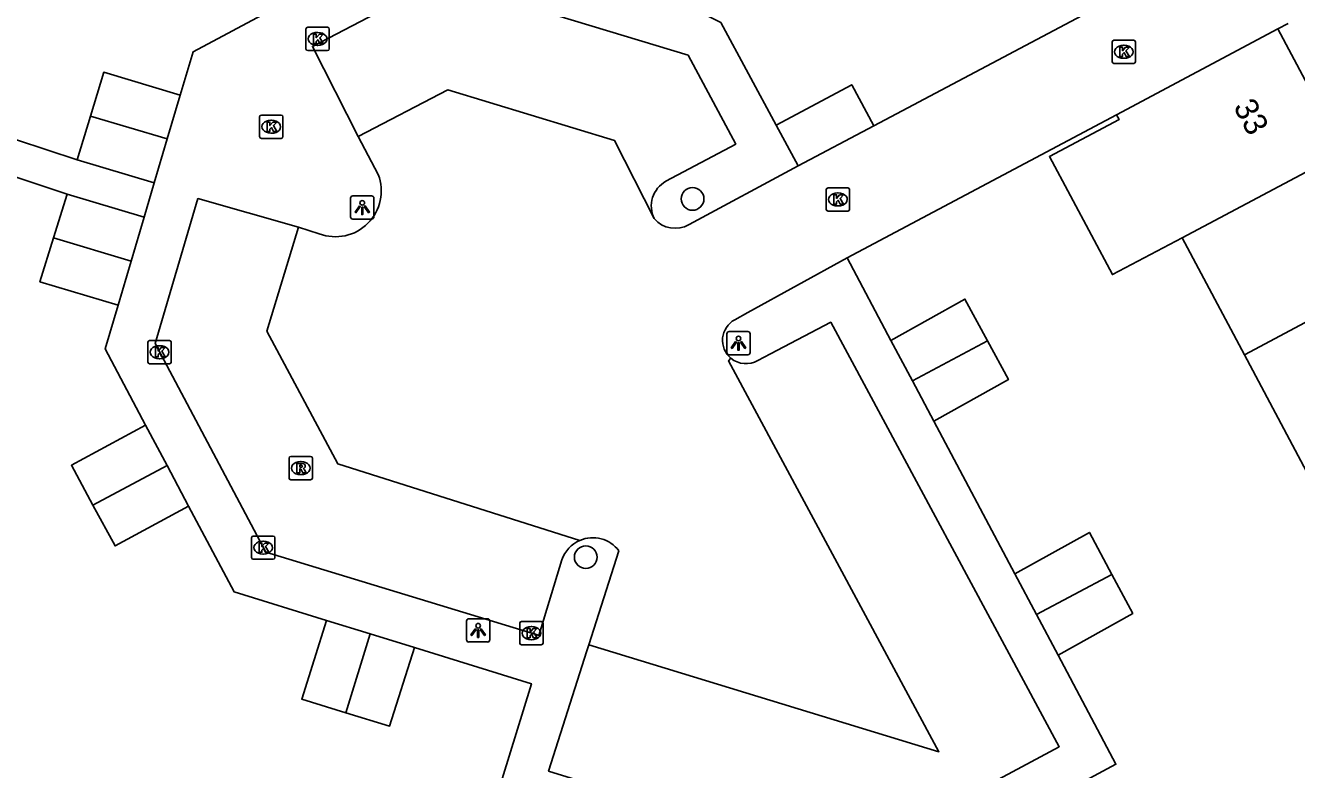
# Model space of a CAD drawing. Extents: x 160304 to 160954, y 383686 to 384161.
# Drawn here: x 160632.9 to 160687.5, y 383830.6 to 383862.6 of the extents above; entities that cross this region are included whole.
import ezdxf

# ---------------------------------------------------------------- set-up
doc = ezdxf.new("R2010")
doc.units = 0
for name, color, linetype in [('IMGEO_Boom', 7, 'Continuous'), ('IMGEO_Kolk', 7, 'Continuous'), ('IMGEO_Lichtpunt', 7, 'Continuous'), ('IMGEO_Pand', 7, 'Continuous'), ('IMGEO_Pand_nummerreeks', 7, 'Continuous'), ('IMGEO_Rijbaan_lokaal_open', 7, 'Continuous'), ('IMGEO_Rioolput', 7, 'Continuous'), ('IMGEO_Voetpad_open', 7, 'Continuous')]:
    doc.layers.add(name, color=color, linetype=linetype)

msp = doc.modelspace()

# ---------------------------------------------------------------- linework, layer by layer
at = {"layer": 'IMGEO_Boom'}
for centre in [(160661.512, 383855.124), (160656.926, 383839.727)]:
    msp.add_circle(centre, 0.489, dxfattribs=at)
at = {"layer": 'IMGEO_Kolk'}
for p, q in [((160644.981, 383862.498), (160645.833, 383862.498)), ((160644.906, 383861.572), (160644.906, 383862.424)), ((160645.394, 383862.278), (160645.419, 383862.278)), ((160645.907, 383862.424), (160645.907, 383861.572)), ((160679.616, 383861.945), (160680.468, 383861.945)), ((160645.833, 383861.498), (160644.981, 383861.498)), ((160645.417, 383861.718), (160645.392, 383861.718)), ((160679.541, 383861.019), (160679.541, 383861.871)), ((160680.029, 383861.725), (160680.054, 383861.725)), ((160680.542, 383861.871), (160680.542, 383861.019)), ((160680.468, 383860.945), (160679.616, 383860.945)), ((160680.052, 383861.165), (160680.027, 383861.165)), ((160642.913, 383857.8), (160642.913, 383858.652)), ((160642.988, 383858.726), (160643.84, 383858.726)), ((160643.914, 383858.652), (160643.914, 383857.8)), ((160643.401, 383858.506), (160643.426, 383858.506)), ((160643.84, 383857.726), (160642.988, 383857.726)), ((160643.424, 383857.946), (160643.399, 383857.946)), ((160667.259, 383854.673), (160667.259, 383855.525)), ((160667.334, 383855.599), (160668.186, 383855.599)), ((160667.747, 383855.379), (160667.772, 383855.379)), ((160668.26, 383855.525), (160668.26, 383854.673)), ((160667.77, 383854.819), (160667.745, 383854.819)), ((160668.186, 383854.599), (160667.334, 383854.599)), ((160638.115, 383848.11), (160638.115, 383848.962)), ((160638.19, 383849.036), (160639.042, 383849.036)), ((160638.603, 383848.816), (160638.628, 383848.816)), ((160639.116, 383848.962), (160639.116, 383848.11)), ((160639.042, 383848.036), (160638.19, 383848.036)), ((160638.626, 383848.256), (160638.601, 383848.256)), ((160642.643, 383840.636), (160643.495, 383840.636)), ((160642.568, 383839.71), (160642.568, 383840.562)), ((160643.056, 383840.416), (160643.081, 383840.416)), ((160643.569, 383840.562), (160643.569, 383839.71)), ((160643.495, 383839.636), (160642.643, 383839.636)), ((160643.079, 383839.856), (160643.054, 383839.856)), ((160654.088, 383836.035), (160654.088, 383836.887)), ((160654.163, 383836.961), (160655.015, 383836.961)), ((160655.089, 383836.887), (160655.089, 383836.035)), ((160654.576, 383836.741), (160654.601, 383836.741)), ((160655.015, 383835.961), (160654.163, 383835.961)), ((160654.599, 383836.181), (160654.574, 383836.181))]:
    msp.add_line(p, q, dxfattribs=at)
for points in [[(160644.981, 383862.498), (160645.833, 383862.498)], [(160644.906, 383861.572), (160644.906, 383862.424)], [(160645.227, 383862.198), (160645.35, 383862.198), (160645.35, 383862.047), (160645.48, 383862.198), (160645.644, 383862.198), (160645.498, 383862.047), (160645.651, 383861.798), (160645.499, 383861.798), (160645.414, 383861.962), (160645.35, 383861.895), (160645.35, 383861.798), (160645.227, 383861.798), (160645.227, 383862.198)], [(160645.907, 383862.424), (160645.907, 383861.572)], [(160679.616, 383861.945), (160680.468, 383861.945)], [(160645.833, 383861.498), (160644.981, 383861.498)], [(160679.541, 383861.019), (160679.541, 383861.871)], [(160679.862, 383861.645), (160679.985, 383861.645), (160679.985, 383861.494), (160680.115, 383861.645), (160680.279, 383861.645), (160680.133, 383861.494), (160680.286, 383861.245), (160680.134, 383861.245), (160680.049, 383861.409), (160679.985, 383861.342), (160679.985, 383861.245), (160679.862, 383861.245), (160679.862, 383861.645)], [(160680.542, 383861.871), (160680.542, 383861.019)], [(160680.468, 383860.945), (160679.616, 383860.945)], [(160642.913, 383857.8), (160642.913, 383858.652)], [(160642.988, 383858.726), (160643.84, 383858.726)], [(160643.914, 383858.652), (160643.914, 383857.8)], [(160643.234, 383858.426), (160643.357, 383858.426), (160643.357, 383858.275), (160643.487, 383858.426), (160643.651, 383858.426), (160643.505, 383858.275), (160643.658, 383858.026), (160643.506, 383858.026), (160643.421, 383858.19), (160643.357, 383858.123), (160643.357, 383858.026), (160643.234, 383858.026), (160643.234, 383858.426)], [(160643.84, 383857.726), (160642.988, 383857.726)], [(160667.259, 383854.673), (160667.259, 383855.525)], [(160667.334, 383855.599), (160668.186, 383855.599)], [(160668.26, 383855.525), (160668.26, 383854.673)], [(160667.58, 383855.299), (160667.703, 383855.299), (160667.703, 383855.148), (160667.833, 383855.299), (160667.997, 383855.299), (160667.851, 383855.148), (160668.004, 383854.899), (160667.852, 383854.899), (160667.767, 383855.063), (160667.703, 383854.996), (160667.703, 383854.899), (160667.58, 383854.899), (160667.58, 383855.299)], [(160668.186, 383854.599), (160667.334, 383854.599)], [(160638.115, 383848.11), (160638.115, 383848.962)], [(160638.19, 383849.036), (160639.042, 383849.036)], [(160639.116, 383848.962), (160639.116, 383848.11)], [(160638.436, 383848.736), (160638.559, 383848.736), (160638.559, 383848.585), (160638.689, 383848.736), (160638.853, 383848.736), (160638.707, 383848.585), (160638.86, 383848.336), (160638.708, 383848.336), (160638.623, 383848.5), (160638.559, 383848.433), (160638.559, 383848.336), (160638.436, 383848.336), (160638.436, 383848.736)], [(160639.042, 383848.036), (160638.19, 383848.036)], [(160642.643, 383840.636), (160643.495, 383840.636)], [(160642.568, 383839.71), (160642.568, 383840.562)], [(160642.889, 383840.336), (160643.012, 383840.336), (160643.012, 383840.185), (160643.142, 383840.336), (160643.306, 383840.336), (160643.16, 383840.185), (160643.313, 383839.936), (160643.161, 383839.936), (160643.076, 383840.1), (160643.012, 383840.033), (160643.012, 383839.936), (160642.889, 383839.936), (160642.889, 383840.336)], [(160643.569, 383840.562), (160643.569, 383839.71)], [(160643.495, 383839.636), (160642.643, 383839.636)], [(160654.088, 383836.035), (160654.088, 383836.887)], [(160654.163, 383836.961), (160655.015, 383836.961)], [(160655.089, 383836.887), (160655.089, 383836.035)], [(160654.409, 383836.661), (160654.532, 383836.661), (160654.532, 383836.51), (160654.662, 383836.661), (160654.826, 383836.661), (160654.68, 383836.51), (160654.833, 383836.261), (160654.681, 383836.261), (160654.596, 383836.425), (160654.532, 383836.358), (160654.532, 383836.261), (160654.409, 383836.261), (160654.409, 383836.661)], [(160655.015, 383835.961), (160654.163, 383835.961)]]:
    msp.add_lwpolyline(points, dxfattribs=at)
for centre, start, end in [((160644.983, 383862.422), 91.552, 178.448), ((160644.983, 383862.422), 91.552, 178.448), ((160645.831, 383862.422), 1.552, 88.448), ((160645.831, 383862.422), 1.552, 88.448), ((160679.618, 383861.869), 91.552, 178.448), ((160679.618, 383861.869), 91.552, 178.448), ((160680.466, 383861.869), 1.552, 88.448), ((160680.466, 383861.869), 1.552, 88.448), ((160644.983, 383861.574), 181.552, 268.448), ((160644.983, 383861.574), 181.552, 268.448), ((160645.831, 383861.574), 271.552, 358.448), ((160645.831, 383861.574), 271.552, 358.448), ((160679.618, 383861.021), 181.552, 268.448), ((160679.618, 383861.021), 181.552, 268.448), ((160680.466, 383861.021), 271.552, 358.448), ((160680.466, 383861.021), 271.552, 358.448), ((160642.99, 383858.65), 91.552, 178.448), ((160642.99, 383858.65), 91.552, 178.448), ((160643.838, 383858.65), 1.552, 88.448), ((160643.838, 383858.65), 1.552, 88.448), ((160642.99, 383857.802), 181.552, 268.448), ((160642.99, 383857.802), 181.552, 268.448), ((160643.838, 383857.802), 271.552, 358.448), ((160643.838, 383857.802), 271.552, 358.448), ((160667.336, 383855.523), 91.552, 178.448), ((160667.336, 383855.523), 91.552, 178.448), ((160668.184, 383855.523), 1.552, 88.448), ((160668.184, 383855.523), 1.552, 88.448), ((160667.336, 383854.675), 181.552, 268.448), ((160667.336, 383854.675), 181.552, 268.448), ((160668.184, 383854.675), 271.552, 358.448), ((160668.184, 383854.675), 271.552, 358.448), ((160638.192, 383848.96), 91.552, 178.448), ((160638.192, 383848.96), 91.552, 178.448), ((160639.04, 383848.96), 1.552, 88.448), ((160639.04, 383848.96), 1.552, 88.448), ((160638.192, 383848.112), 181.552, 268.448), ((160638.192, 383848.112), 181.552, 268.448), ((160639.04, 383848.112), 271.552, 358.448), ((160639.04, 383848.112), 271.552, 358.448), ((160642.645, 383840.56), 91.552, 178.448), ((160642.645, 383840.56), 91.552, 178.448), ((160643.493, 383840.56), 1.552, 88.448), ((160643.493, 383840.56), 1.552, 88.448), ((160642.645, 383839.712), 181.552, 268.448), ((160642.645, 383839.712), 181.552, 268.448), ((160643.493, 383839.712), 271.552, 358.448), ((160643.493, 383839.712), 271.552, 358.448), ((160654.165, 383836.885), 91.552, 178.448), ((160654.165, 383836.885), 91.552, 178.448), ((160655.013, 383836.885), 1.552, 88.448), ((160655.013, 383836.885), 1.552, 88.448), ((160654.165, 383836.037), 181.552, 268.448), ((160654.165, 383836.037), 181.552, 268.448), ((160655.013, 383836.037), 271.552, 358.448), ((160655.013, 383836.037), 271.552, 358.448)]:
    msp.add_arc(centre, 0.0765, start, end, dxfattribs=at)
for centre, major_axis, ratio, start_param, end_param in [((160645.393, 383861.998), (-0.387, 0.002), 0.722429, 4.712389, 7.853982), ((160645.418, 383861.998), (-0.39, 0.002), 0.717154, 1.570796, 4.712389), ((160680.028, 383861.445), (-0.387, 0.002), 0.722429, 4.712389, 7.853982), ((160680.053, 383861.445), (-0.39, 0.002), 0.717154, 1.570796, 4.712389), ((160643.4, 383858.226), (-0.387, 0.002), 0.722429, 4.712389, 7.853982), ((160643.425, 383858.226), (-0.39, 0.002), 0.717154, 1.570796, 4.712389), ((160667.746, 383855.099), (-0.387, 0.002), 0.722429, 4.712389, 7.853982), ((160667.771, 383855.099), (-0.39, 0.002), 0.717154, 1.570796, 4.712389), ((160638.602, 383848.536), (-0.387, 0.002), 0.722429, 4.712389, 7.853982), ((160638.627, 383848.536), (-0.39, 0.002), 0.717154, 1.570796, 4.712389), ((160643.055, 383840.136), (-0.387, 0.002), 0.722429, 4.712389, 7.853982), ((160643.08, 383840.136), (-0.39, 0.002), 0.717154, 1.570796, 4.712389), ((160654.575, 383836.461), (-0.387, 0.002), 0.722429, 4.712389, 7.853982), ((160654.6, 383836.461), (-0.39, 0.002), 0.717154, 1.570796, 4.712389)]:
    msp.add_ellipse(centre, major_axis=major_axis, ratio=ratio, start_param=start_param, end_param=end_param, dxfattribs=at)
at = {"layer": 'IMGEO_Lichtpunt'}
for p, q in [((160646.825, 383855.156), (160646.825, 383854.349)), ((160646.825, 383855.156), (160646.825, 383854.349)), ((160647.727, 383855.251), (160646.919, 383855.251)), ((160647.727, 383855.251), (160646.919, 383855.251)), ((160647.821, 383854.349), (160647.821, 383855.156)), ((160647.821, 383854.349), (160647.821, 383855.156)), ((160646.919, 383854.255), (160647.727, 383854.255)), ((160646.919, 383854.255), (160647.727, 383854.255)), ((160663.891, 383849.421), (160663.083, 383849.421)), ((160663.891, 383849.421), (160663.083, 383849.421)), ((160662.989, 383849.326), (160662.989, 383848.519)), ((160662.989, 383849.326), (160662.989, 383848.519)), ((160663.985, 383848.519), (160663.985, 383849.326)), ((160663.985, 383848.519), (160663.985, 383849.326)), ((160663.083, 383848.425), (160663.891, 383848.425)), ((160663.083, 383848.425), (160663.891, 383848.425)), ((160651.804, 383836.983), (160651.804, 383836.176)), ((160651.804, 383836.983), (160651.804, 383836.176)), ((160652.706, 383837.078), (160651.898, 383837.078)), ((160652.706, 383837.078), (160651.898, 383837.078)), ((160652.8, 383836.176), (160652.8, 383836.983)), ((160652.8, 383836.176), (160652.8, 383836.983)), ((160651.898, 383836.082), (160652.706, 383836.082)), ((160651.898, 383836.082), (160652.706, 383836.082))]:
    msp.add_line(p, q, dxfattribs=at)
for points in [[(160647.199, 383854.82), (160647.238, 383854.792), (160647.05, 383854.53), (160647.012, 383854.557), (160647.199, 383854.82)], [(160647.411, 383854.792), (160647.449, 383854.819), (160647.636, 383854.557), (160647.597, 383854.529), (160647.411, 383854.792)], [(160647.301, 383854.772), (160647.348, 383854.772), (160647.348, 383854.45), (160647.301, 383854.45), (160647.301, 383854.772)], [(160663.363, 383848.99), (160663.402, 383848.962), (160663.214, 383848.7), (160663.176, 383848.727), (160663.363, 383848.99)], [(160663.465, 383848.942), (160663.512, 383848.942), (160663.512, 383848.62), (160663.465, 383848.62), (160663.465, 383848.942)], [(160663.575, 383848.962), (160663.613, 383848.989), (160663.8, 383848.727), (160663.761, 383848.699), (160663.575, 383848.962)], [(160652.178, 383836.647), (160652.217, 383836.619), (160652.029, 383836.357), (160651.991, 383836.384), (160652.178, 383836.647)], [(160652.28, 383836.599), (160652.327, 383836.599), (160652.327, 383836.277), (160652.28, 383836.277), (160652.28, 383836.599)], [(160652.39, 383836.619), (160652.428, 383836.646), (160652.615, 383836.384), (160652.576, 383836.356), (160652.39, 383836.619)]]:
    msp.add_lwpolyline(points, dxfattribs=at)
for centre in [(160647.324, 383854.954), (160663.488, 383849.124), (160652.303, 383836.781)]:
    msp.add_circle(centre, 0.0994, dxfattribs=at)
for centre, start, end in [((160646.919, 383855.156), 90, 180), ((160646.919, 383855.156), 90, 180), ((160647.727, 383855.156), 0, 90), ((160647.727, 383855.156), 0, 90), ((160646.919, 383854.349), 180, 270), ((160646.919, 383854.349), 180, 270), ((160647.727, 383854.349), 270, 0), ((160647.727, 383854.349), 270, 360), ((160663.083, 383849.326), 90, 180), ((160663.083, 383849.326), 90, 180), ((160663.891, 383849.326), 0, 90), ((160663.891, 383849.326), 0, 90), ((160663.083, 383848.519), 180, 270), ((160663.083, 383848.519), 180, 270), ((160663.891, 383848.519), 270, 0), ((160663.891, 383848.519), 270, 360), ((160651.898, 383836.983), 90, 180), ((160651.898, 383836.983), 90, 180), ((160652.706, 383836.983), 0, 90), ((160652.706, 383836.983), 0, 90), ((160651.898, 383836.176), 180, 270), ((160651.898, 383836.176), 180, 270), ((160652.706, 383836.176), 270, 0), ((160652.706, 383836.176), 270, 360)]:
    msp.add_arc(centre, 0.0946, start, end, dxfattribs=at)
at = {"layer": 'IMGEO_Pand'}
for points in [[(160686.663, 383862.43), (160679.729, 383858.737)], [(160689.481, 383857.138), (160686.663, 383862.43)], [(160635.644, 383858.686), (160636.219, 383860.57), (160639.506, 383859.586)], [(160665.106, 383858.297), (160668.35, 383860.032), (160669.297, 383858.262)], [(160639.506, 383859.586), (160638.947, 383857.698)], [(160635.069, 383856.802), (160635.644, 383858.686)], [(160638.947, 383857.698), (160635.644, 383858.686)], [(160679.729, 383858.737), (160679.836, 383858.535), (160676.845, 383856.942), (160679.547, 383851.868), (160682.541, 383853.456)], [(160666.055, 383856.543), (160665.106, 383858.297)], [(160669.297, 383858.262), (160666.055, 383856.543)], [(160638.947, 383857.698), (160638.388, 383855.809)], [(160682.541, 383853.456), (160689.481, 383857.138)], [(160638.388, 383855.809), (160635.069, 383856.802)], [(160634.058, 383853.448), (160634.642, 383855.331)], [(160634.642, 383855.331), (160637.955, 383854.343)], [(160637.955, 383854.343), (160637.396, 383852.452)], [(160636.837, 383850.561), (160633.474, 383851.564), (160634.058, 383853.448)], [(160634.058, 383853.448), (160637.396, 383852.452)], [(160682.541, 383853.456), (160685.222, 383848.423)], [(160637.396, 383852.452), (160636.837, 383850.561)], [(160685.222, 383848.423), (160692.156, 383852.115)], [(160674.186, 383849.023), (160673.216, 383850.817), (160670.036, 383849.043)], [(160670.956, 383847.31), (160670.036, 383849.043)], [(160674.186, 383849.023), (160670.956, 383847.31)], [(160671.878, 383845.572), (160675.085, 383847.361), (160674.186, 383849.023)], [(160685.222, 383848.423), (160687.891, 383843.41)], [(160671.878, 383845.572), (160670.956, 383847.31)], [(160635.753, 383841.969), (160634.828, 383843.676), (160638.017, 383845.404)], [(160638.017, 383845.404), (160638.941, 383843.661)], [(160635.753, 383841.969), (160638.941, 383843.661)], [(160638.941, 383843.661), (160639.864, 383841.919)], [(160639.864, 383841.919), (160636.708, 383840.209), (160635.753, 383841.969)], [(160679.531, 383838.979), (160678.564, 383840.791), (160675.364, 383839.006)], [(160676.289, 383837.262), (160675.364, 383839.006)], [(160676.289, 383837.262), (160679.531, 383838.979)], [(160677.215, 383835.517), (160680.423, 383837.307), (160679.531, 383838.979)], [(160646.621, 383833.04), (160644.721, 383833.621), (160645.787, 383837.008)], [(160645.787, 383837.008), (160647.67, 383836.426)], [(160677.215, 383835.517), (160676.289, 383837.262)], [(160647.67, 383836.426), (160646.621, 383833.04)], [(160647.67, 383836.426), (160649.562, 383835.841)], [(160649.562, 383835.841), (160648.5, 383832.466), (160646.621, 383833.04)]]:
    msp.add_lwpolyline(points, dxfattribs=at)
at = {"layer": 'IMGEO_Rijbaan_lokaal_open'}
for points in [[(160669.297, 383858.262), (160685.008, 383866.594)], [(160686.663, 383862.43), (160687.096, 383862.66)], [(160647.154, 383857.81), (160650.995, 383859.816), (160658.161, 383857.635), (160659.864, 383854.277)], [(160668.151, 383852.596), (160679.729, 383858.737)], [(160648.012, 383856.169), (160647.154, 383857.81)], [(160661.361, 383854.018), (160666.055, 383856.543)], [(160656.67, 383840.446), (160646.268, 383843.745), (160643.228, 383849.443), (160644.589, 383853.907)], [(160644.589, 383853.907), (160645.477, 383853.625)], [(160668.151, 383852.596), (160663.89, 383850.24), (160663.326, 383849.928)], [(160657.06, 383835.957), (160672.095, 383831.365), (160663.061, 383848.16), (160663.159, 383848.277)], [(160657.06, 383835.957), (160658.353, 383839.999)]]:
    msp.add_lwpolyline(points, dxfattribs=at)
for centre, radius, start, end in [((160646.174, 383855.465), 1.968, 249.2499, 20.9531), ((160660.769, 383855.052), 1.192, 220.584, 299.7846), ((160663.805, 383849.046), 1.004, 118.4948, 229.9535), ((160657.229, 383839.16), 1.402, 36.7434, 113.5082)]:
    msp.add_arc(centre, radius, start, end, dxfattribs=at)
at = {"layer": 'IMGEO_Rioolput'}
for p, q in [((160644.18, 383843.129), (160644.18, 383843.981)), ((160644.255, 383844.055), (160645.107, 383844.055)), ((160645.181, 383843.981), (160645.181, 383843.129)), ((160644.668, 383843.835), (160644.693, 383843.835)), ((160645.107, 383843.055), (160644.255, 383843.055)), ((160644.691, 383843.275), (160644.666, 383843.275))]:
    msp.add_line(p, q, dxfattribs=at)
for points in [[(160644.18, 383843.129), (160644.18, 383843.981)], [(160644.255, 383844.055), (160645.107, 383844.055)], [(160645.181, 383843.981), (160645.181, 383843.129)], [(160644.769, 383843.753), (160644.517, 383843.755), (160644.517, 383843.355)], [(160644.517, 383843.355), (160644.641, 383843.355), (160644.641, 383843.517), (160644.652, 383843.517)], [(160644.695, 383843.674), (160644.641, 383843.674), (160644.641, 383843.593)], [(160644.641, 383843.593), (160644.693, 383843.593)], [(160644.699, 383843.488), (160644.77, 383843.355), (160644.91, 383843.355), (160644.845, 383843.481)], [(160645.107, 383843.055), (160644.255, 383843.055)]]:
    msp.add_lwpolyline(points, dxfattribs=at)
for centre, radius, start, end in [((160644.257, 383843.979), 0.0765, 91.552, 178.448), ((160644.257, 383843.979), 0.0765, 91.552, 178.448), ((160645.105, 383843.979), 0.0765, 1.552, 88.448), ((160645.105, 383843.979), 0.0765, 1.552, 88.448), ((160644.651, 383843.464), 0.0533, 26.0293, 88.6989), ((160644.677, 383843.782), 0.19, 274.7715, 282.9687), ((160644.701, 383843.578), 0.0964, 77.0061, 93.1865), ((160644.715, 383843.635), 0.0378, 276.6634, 79.6772), ((160644.768, 383843.643), 0.109, 350.3612, 89.416), ((160644.766, 383843.643), 0.112, 277.5842, 350.9817), ((160644.75, 383843.428), 0.108, 29.5134, 73.7905), ((160644.257, 383843.131), 0.0765, 181.552, 268.448), ((160644.257, 383843.131), 0.0765, 181.552, 268.448), ((160645.105, 383843.131), 0.0765, 271.552, 358.448), ((160645.105, 383843.131), 0.0765, 271.552, 358.448)]:
    msp.add_arc(centre, radius, start, end, dxfattribs=at)
for centre, major_axis, ratio, start_param, end_param in [((160644.667, 383843.555), (-0.387, 0.002), 0.722429, 4.712389, 7.853982), ((160644.692, 383843.555), (-0.39, 0.002), 0.717154, 1.570796, 4.712389)]:
    msp.add_ellipse(centre, major_axis=major_axis, ratio=ratio, start_param=start_param, end_param=end_param, dxfattribs=at)
at = {"layer": 'IMGEO_Voetpad_open'}
for points in [[(160660.368, 383855.882), (160663.366, 383857.479), (160661.32, 383861.3), (160658.581, 383862.138), (160650.651, 383864.543), (160645.18, 383861.678), (160647.154, 383857.81)], [(160639.506, 383859.586), (160640.057, 383861.451), (160643.442, 383863.255)], [(160661.192, 383863.479), (160662.724, 383862.698), (160665.106, 383858.297)], [(160626.502, 383858.047), (160625.638, 383858.3), (160625.326, 383859.284), (160626.186, 383859.758), (160627.249, 383859.386), (160635.069, 383856.802)], [(160634.642, 383855.331), (160629.872, 383856.923)], [(160637.955, 383854.343), (160638.388, 383855.809)], [(160655.903, 383839.619), (160654.907, 383836.365), (160654.789, 383836.401), (160643.175, 383839.939), (160638.422, 383848.904), (160640.26, 383855.134), (160644.589, 383853.907)], [(160670.036, 383849.043), (160668.151, 383852.596)], [(160638.017, 383845.404), (160636.28, 383848.678), (160636.837, 383850.561)], [(160664.319, 383848.183), (160664.855, 383848.464), (160667.453, 383849.822), (160677.266, 383831.583), (160668.018, 383826.622), (160655.326, 383830.534), (160656.978, 383835.701), (160657.06, 383835.957)], [(160675.364, 383839.006), (160671.878, 383845.572)], [(160645.787, 383837.008), (160641.818, 383838.236), (160639.864, 383841.919)], [(160653.036, 383829.224), (160654.59, 383834.285), (160649.562, 383835.841)], [(160677.836, 383829.832), (160679.704, 383830.827), (160677.215, 383835.517)]]:
    msp.add_lwpolyline(points, dxfattribs=at)
for centre, radius, start, end in [((160660.966, 383854.813), 1.225, 119.1988, 205.9347), ((160663.805, 383849.047), 1.005, 229.9853, 300.7491), ((160657.23, 383839.157), 1.405, 113.4885, 160.8228)]:
    msp.add_arc(centre, radius, start, end, dxfattribs=at)

# ---------------------------------------------------------------- texts
at = {"layer": 'IMGEO_Pand_nummerreeks'}
msp.add_text('33', height=1, rotation=298.0346, dxfattribs=at).set_placement((160684.727, 383859.087))

doc.saveas('drawing.dxf')
